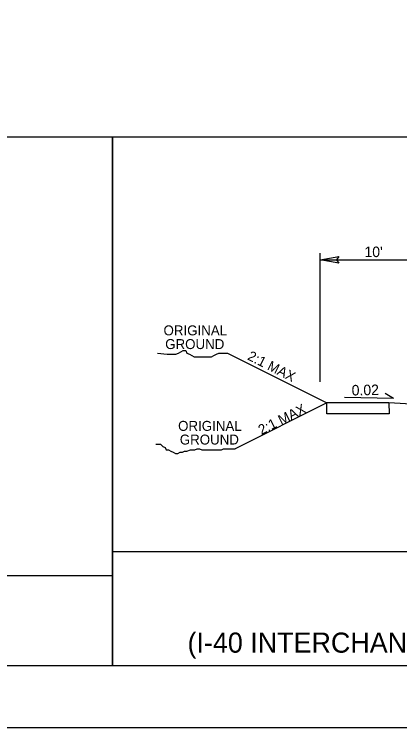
# Model space of a CAD drawing. Extents: x 1636954 to 1644154, y 841334 to 845582.
# Drawn here: x 1640773 to 1641083, y 841334 to 841909 of the extents above; entities that cross this region are included whole.
import ezdxf

# ---------------------------------------------------------------- set-up
doc = ezdxf.new("R2010")
doc.units = 0
for name, color, linetype in [('Prop Dimension', 7, 'Continuous'), ('Prop Lane Lines', 7, 'Continuous'), ('Prop PHM Legend CELL', 7, 'Continuous'), ('Scratch_Level_1', 7, 'Continuous'), ('Sheet Plan And Profile CELL', 7, 'Continuous'), ('Typical Hinge Slope Arterial CELL', 7, 'Continuous'), ('Typical Hinge Slope Interstate CELL', 7, 'Continuous'), ('Typical Pavement Slope Information CELL', 7, 'Continuous'), ('Typical Shoulder Slope CELL', 7, 'Continuous'), ('Typical Text General CELL', 7, 'Continuous')]:
    doc.layers.add(name, color=color, linetype=linetype)

msp = doc.modelspace()

# ---------------------------------------------------------------- linework, layer by layer
at = {"layer": 'Prop Dimension'}
for p, q in [((1641019.13, 841612.57), (1641019.13, 841716.45)), ((1641019.13, 841710.89), (1641103.5, 841710.89))]:
    msp.add_line(p, q, dxfattribs=at)
msp.add_lwpolyline([(1641034.16, 841708.3), (1641019.13, 841710.89), (1641034.25, 841713.56), (1641032.32, 841710.89)], close=True, dxfattribs=at)
at = {"layer": 'Prop PHM Legend CELL'}
for p, q in [((1640851.71, 841475.99), (1641579.63, 841475.99)), ((1637654.2, 841456.59), (1640851.71, 841456.59))]:
    msp.add_line(p, q, dxfattribs=at)
for points in [[(1639599.45, 841810.2), (1640851.71, 841810.2), (1640851.71, 841383.94), (1639599.45, 841383.94)], [(1640851.71, 841810.2), (1641579.63, 841810.2), (1641579.63, 841383.94), (1640851.71, 841383.94)]]:
    msp.add_lwpolyline(points, close=True, dxfattribs=at)
at = {"layer": 'Scratch_Level_1'}
msp.add_lwpolyline([(1636954.2, 841333.94), (1636954.2, 844733.94), (1644154.2, 844733.94), (1644154.2, 841333.94)], close=True, dxfattribs=at)
at = {"layer": 'Sheet Plan And Profile CELL'}
msp.add_lwpolyline([(1637004.2, 841383.94), (1637004.2, 844683.94), (1644104.2, 844683.94), (1644104.2, 841383.94)], close=True, dxfattribs=at)
at = {"layer": 'Typical Hinge Slope Arterial CELL'}
msp.add_lwpolyline([(1640888.08, 841635.85), (1640895.98, 841634.87), (1640897.95, 841634.87), (1640900.92, 841634.87), (1640902.89, 841634.87), (1640904.87, 841635.85), (1640906.84, 841636.84), (1640908.82, 841637.83), (1640910.79, 841637.83), (1640911.78, 841635.85), (1640913.76, 841634.87), (1640915.73, 841633.88), (1640917.71, 841632.89), (1640919.68, 841632.89), (1640921.66, 841632.89), (1640923.63, 841632.89), (1640925.61, 841632.89), (1640927.58, 841632.89), (1640929.56, 841632.89), (1640931.53, 841632.89), (1640933.51, 841633.88), (1640935.48, 841634.87), (1640937.46, 841635.85), (1640940.42, 841635.85), (1640942.4, 841635.85), (1640944.37, 841635.85)], dxfattribs=at)
at = {"layer": 'Typical Hinge Slope Interstate CELL'}
for p, q in [((1640944.37, 841635.85), (1641024.53, 841595.77)), ((1641024.53, 841595.77), (1640950.59, 841558.69))]:
    msp.add_line(p, q, dxfattribs=at)
msp.add_lwpolyline([(1640886.84, 841562.38), (1640888.68, 841562.38), (1640890.53, 841562.38), (1640892.38, 841560.54), (1640894.23, 841559.61), (1640895.15, 841557.76), (1640897, 841557.76), (1640898.85, 841556.84), (1640900.7, 841555.91), (1640902.54, 841554.99), (1640904.39, 841554.99), (1640906.24, 841555.91), (1640908.09, 841555.91), (1640909.94, 841556.84), (1640911.78, 841556.84), (1640914.56, 841557.76), (1640916.41, 841557.76), (1640918.25, 841557.76), (1640920.1, 841558.69), (1640921.95, 841558.69), (1640923.8, 841557.76), (1640925.65, 841557.76), (1640927.49, 841557.76), (1640929.34, 841557.76), (1640931.19, 841557.76), (1640933.96, 841557.76), (1640936.73, 841557.76), (1640939.51, 841557.76), (1640941.36, 841558.69), (1640944.12, 841558.69), (1640946.9, 841558.69), (1640950.59, 841558.69)], dxfattribs=at)
at = {"layer": 'Typical Pavement Slope Information CELL'}
for q in [(1641038.86, 841599.94), (1641071.58, 841603.15)]:
    msp.add_line((1641078.18, 841599.16), q, dxfattribs=at)
at = {"layer": 'Typical Shoulder Slope CELL'}
for p, q in [((1641074.63, 841595.77), (1641024.53, 841595.77)), ((1641024.53, 841586.99), (1641024.53, 841595.77)), ((1641099.49, 841594.34), (1641074.63, 841595.77)), ((1641074.63, 841595.77), (1641074.83, 841586.99)), ((1641074.83, 841586.99), (1641024.53, 841586.99))]:
    msp.add_line(p, q, dxfattribs=at)

# ---------------------------------------------------------------- texts
at = {"layer": 'Prop Dimension'}
msp.add_text("10'", height=8.437, rotation=360, dxfattribs=at).set_placement((1641054.87, 841713.18))
at = {"layer": 'Prop Lane Lines'}
for s, p in [('ORIGINAL', (1640892.92, 841650.1)), ('GROUND', (1640894.27, 841639.07)), ('ORIGINAL', (1640904.68, 841573.15)), ('GROUND', (1640906.03, 841562.13))]:
    msp.add_text(s, height=8.016, dxfattribs=at).set_placement(p)
at = {"layer": 'Typical Hinge Slope Interstate CELL'}
for rotation, p in [(333.43542, (1640959.89, 841630.87)), (26.56458, (1640971.74, 841569.76))]:
    msp.add_text('2:1 MAX', height=8.016, rotation=rotation, dxfattribs=at).set_placement(p)
at = {"layer": 'Typical Pavement Slope Information CELL'}
msp.add_text('0.02', height=8.438, rotation=1.14574, dxfattribs=at).set_placement((1641044.64, 841601.65))
at = {"layer": 'Typical Text General CELL'}
msp.add_text('(I-40 INTERCHANGE NORTH TO CLEMMONSVILLE RD)', height=16.2, dxfattribs=at).set_placement((1640912.27, 841394.41))

doc.saveas('drawing.dxf')
